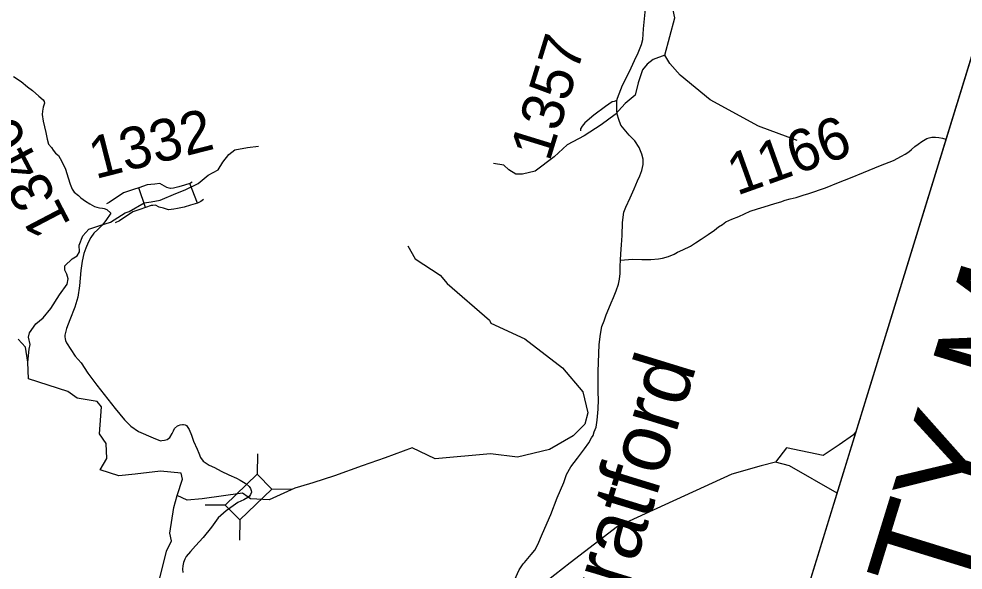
# Model space of a CAD drawing. Extents: x 1347947 to 1350662, y 1027710 to 1030532.
# Drawn here: x 1348252.2 to 1348353.5, y 1028872.1 to 1028931.2 of the extents above; entities that cross this region are included whole.
import ezdxf

# ---------------------------------------------------------------- set-up
doc = ezdxf.new("R2010")
doc.units = 0
for name, color, linetype in [('Default', 7, 'Continuous'), ('Prop Leader Line Light', 7, 'Continuous'), ('Prop WCC CELL', 7, 'Continuous')]:
    doc.layers.add(name, color=color, linetype=linetype)

msp = doc.modelspace()

# ---------------------------------------------------------------- linework, layer by layer
at = {"layer": 'Default'}
for p, q in [((1348271.33, 1028911.43), (1348270.53, 1028913.54)), ((1348265.77, 1028910.96), (1348265.04, 1028913.09)), ((1348277.79, 1028884.53), (1348277.76, 1028882.36)), ((1348281.49, 1028880.72), (1348279.31, 1028880.76)), ((1348274.36, 1028879.01), (1348272.18, 1028879.04)), ((1348275.88, 1028877.45), (1348275.84, 1028875.27))]:
    msp.add_line(p, q, dxfattribs=at)
for points in [[(1348335.7, 1028918.15), (1348331.55, 1028919.69), (1348326.36, 1028922.53), (1348323.14, 1028925.18), (1348322.03, 1028926.42), (1348321.51, 1028927.31), (1348322.57, 1028931.33), (1348321.95, 1028934.18), (1348322.52, 1028936.78), (1348322.2, 1028941.24), (1348321.28, 1028949.45), (1348318.58, 1028951.79), (1348317.29, 1028954.5)], [(1348316.36, 1028922.46), (1348316.42, 1028922.69), (1348316.97, 1028924.08), (1348317.69, 1028925.56), (1348318.26, 1028926.75), (1348318.64, 1028927.55), (1348318.98, 1028928.47), (1348319.13, 1028929.01), (1348319.2, 1028930.15), (1348319.42, 1028932.29)], [(1348321.51, 1028927.31), (1348320.24, 1028926.84), (1348319.6, 1028926.35), (1348319.09, 1028925.75), (1348318.65, 1028924.34), (1348318.3, 1028923.03), (1348317.24, 1028922.12), (1348316.18, 1028920.96), (1348314.67, 1028919.85), (1348312.83, 1028918.66), (1348311.02, 1028917.69), (1348309.63, 1028916.4), (1348307.57, 1028914.88), (1348306.22, 1028914.53), (1348305.51, 1028914.54), (1348304.76, 1028915.01), (1348304.22, 1028915.5), (1348303.1, 1028915.69)], [(1348251.59, 1028925.02), (1348252.41, 1028924.5), (1348253.09, 1028923.93), (1348253.64, 1028923.51), (1348254.31, 1028922.93), (1348254.77, 1028922.52), (1348254.89, 1028922.36), (1348254.92, 1028922.15), (1348254.77, 1028921.72), (1348254.7, 1028921.32), (1348254.69, 1028920.94), (1348254.77, 1028920.24), (1348255.06, 1028919.01), (1348255.21, 1028918.29), (1348255.37, 1028917.76), (1348255.66, 1028917.39), (1348255.86, 1028917.13), (1348256.12, 1028916.81), (1348256.42, 1028916.54), (1348256.59, 1028916.23), (1348256.75, 1028915.99), (1348257.19, 1028915.09), (1348257.48, 1028914.14), (1348257.67, 1028913.48), (1348257.9, 1028912.93), (1348258.12, 1028912.61), (1348258.56, 1028912.27), (1348258.82, 1028912.02), (1348259.34, 1028911.65), (1348259.78, 1028911.38), (1348260.3, 1028911.08), (1348260.56, 1028910.99), (1348260.84, 1028910.93), (1348261.15, 1028910.88), (1348261.33, 1028910.86), (1348261.62, 1028910.76), (1348262.05, 1028910.35)], [(1348316.36, 1028922.46), (1348316.06, 1028922.35), (1348315.86, 1028922.32), (1348315.12, 1028921.81), (1348313.89, 1028920.86), (1348312.91, 1028920.05), (1348312.61, 1028919.69), (1348312.45, 1028919.4), (1348312.43, 1028919.2)], [(1348316.74, 1028905.33), (1348316.79, 1028905.98), (1348316.85, 1028906.95), (1348316.92, 1028907.97), (1348316.96, 1028909.35), (1348317.11, 1028910.48), (1348317.3, 1028911.02), (1348317.77, 1028912.02), (1348318.19, 1028912.97), (1348318.57, 1028913.84), (1348318.81, 1028914.38), (1348319.03, 1028914.95), (1348319.19, 1028915.57), (1348319.17, 1028916.14), (1348319.04, 1028916.71), (1348318.76, 1028917.41), (1348318.28, 1028918.13), (1348317.68, 1028918.73), (1348317.12, 1028919.37), (1348316.78, 1028919.81), (1348316.56, 1028920.41), (1348316.39, 1028920.98), (1348316.35, 1028921.46), (1348316.36, 1028922.46)], [(1348316.74, 1028905.33), (1348318.01, 1028905.41), (1348319.02, 1028905.39), (1348320, 1028905.4), (1348320.83, 1028905.46), (1348321.24, 1028905.54), (1348321.89, 1028905.71), (1348322.5, 1028905.97), (1348322.85, 1028906.16), (1348323.44, 1028906.44), (1348324.25, 1028906.81), (1348324.8, 1028907.17), (1348325.41, 1028907.57), (1348326.15, 1028908.07), (1348326.82, 1028908.53), (1348327.27, 1028908.88), (1348327.7, 1028909.14), (1348328.06, 1028909.42), (1348328.7, 1028909.73), (1348329.44, 1028910.02), (1348330.65, 1028910.56), (1348331.46, 1028910.81), (1348332.17, 1028911.05), (1348332.72, 1028911.22), (1348333.29, 1028911.4), (1348333.93, 1028911.56), (1348334.41, 1028911.74), (1348334.96, 1028911.9), (1348335.58, 1028912.05), (1348336.34, 1028912.31), (1348336.94, 1028912.46), (1348338.73, 1028913.07), (1348340.12, 1028913.66), (1348341.41, 1028914.16), (1348342.82, 1028914.73), (1348344.65, 1028915.48), (1348346.02, 1028916.02), (1348346.89, 1028916.46), (1348347.28, 1028916.71), (1348347.67, 1028916.96), (1348347.98, 1028917.2), (1348348.33, 1028917.51), (1348348.68, 1028917.76), (1348349.07, 1028918.04), (1348349.42, 1028918.28), (1348349.62, 1028918.39), (1348349.88, 1028918.46), (1348350.16, 1028918.52), (1348350.53, 1028918.51), (1348350.9, 1028918.48), (1348351.29, 1028918.4), (1348351.66, 1028918.31), (1348351.69, 1028918.31)], [(1348253.12, 1028894.38), (1348253.29, 1028895.78), (1348253.39, 1028896.26), (1348253.22, 1028897.04), (1348253.32, 1028897.51), (1348253.99, 1028898.5), (1348254.8, 1028899.13), (1348255.61, 1028900.13), (1348256.52, 1028901.59), (1348257.35, 1028902.73), (1348257.45, 1028903.3), (1348257.32, 1028903.81), (1348257.1, 1028904.24), (1348257.12, 1028904.7), (1348257.9, 1028905.45), (1348258.42, 1028905.78), (1348258.67, 1028906.2), (1348258.65, 1028906.92), (1348259.05, 1028907.94), (1348259.7, 1028908.63), (1348260.86, 1028909.04), (1348262.02, 1028909.41), (1348263.58, 1028910.39), (1348264, 1028910.55), (1348265.61, 1028911.46), (1348266.36, 1028911.56), (1348267.34, 1028911.75), (1348269.02, 1028912.48), (1348270.03, 1028912.85), (1348271.41, 1028913.53), (1348272.5, 1028914.43), (1348273.58, 1028915.01), (1348274.08, 1028915.85), (1348274.71, 1028916.65), (1348275.35, 1028917.14), (1348276.7, 1028917.39), (1348277.89, 1028917.54)], [(1348270.76, 1028913.69), (1348270.58, 1028913.57), (1348270.53, 1028913.54), (1348269.96, 1028913.38), (1348269.33, 1028913.19), (1348268.77, 1028913.06), (1348268.47, 1028913.02), (1348268.44, 1028913.01), (1348268.3, 1028913.05), (1348268.06, 1028913.11), (1348267.32, 1028913.54), (1348266.77, 1028913.48), (1348266.35, 1028913.43), (1348265.93, 1028913.41), (1348265.04, 1028913.09), (1348264.46, 1028912.9), (1348263.39, 1028912.54), (1348261.86, 1028911.5), (1348261.59, 1028911.37)], [(1348272, 1028911.81), (1348271.7, 1028911.61), (1348271.33, 1028911.43), (1348270.59, 1028911.22), (1348269.9, 1028911.01), (1348269.19, 1028910.85), (1348268.81, 1028910.79), (1348268.25, 1028910.71), (1348267.7, 1028910.88), (1348267.22, 1028911), (1348266.84, 1028911.22), (1348266.54, 1028911.18), (1348266.38, 1028911.18), (1348265.77, 1028910.96), (1348265.17, 1028910.76), (1348264.4, 1028910.5), (1348262.97, 1028909.53), (1348262.52, 1028909.33)], [(1348262.05, 1028910.35), (1348261.51, 1028909.58), (1348261.1, 1028909.07), (1348260.64, 1028908.62), (1348260.23, 1028908.21), (1348259.89, 1028907.74), (1348259.6, 1028907.21), (1348259.37, 1028906.6), (1348259.16, 1028906.02), (1348258.97, 1028905.21), (1348258.82, 1028904.2), (1348258.67, 1028902.56), (1348258.51, 1028901.33), (1348258.19, 1028900.28), (1348257.65, 1028898.92), (1348257.28, 1028897.97), (1348257.12, 1028897.27), (1348257.1, 1028897.09), (1348257.13, 1028896.88), (1348257.19, 1028896.7), (1348257.3, 1028896.43), (1348258.22, 1028895.03), (1348258.86, 1028894.31), (1348259.57, 1028893.2), (1348260.53, 1028891.91), (1348262.5, 1028889.41), (1348263.5, 1028888.18), (1348264.19, 1028887.51), (1348265, 1028886.92), (1348266.58, 1028886.24), (1348267.36, 1028885.93), (1348267.53, 1028885.95), (1348267.81, 1028885.99), (1348267.95, 1028886.02), (1348268.08, 1028886.09), (1348268.22, 1028886.18), (1348268.37, 1028886.27), (1348268.62, 1028886.71), (1348268.77, 1028887.02), (1348268.89, 1028887.24), (1348269.2, 1028887.54), (1348269.29, 1028887.57), (1348269.47, 1028887.63), (1348269.73, 1028887.69), (1348269.84, 1028887.67), (1348270.01, 1028887.65), (1348270.17, 1028887.57), (1348270.45, 1028887.15), (1348270.69, 1028886.55), (1348270.93, 1028885.9), (1348271.31, 1028885.05), (1348271.5, 1028884.6), (1348271.67, 1028884.14), (1348271.94, 1028883.74), (1348272.29, 1028883.53), (1348272.6, 1028883.3), (1348273.16, 1028883.07), (1348273.9, 1028882.68), (1348274.69, 1028882.29), (1348275.52, 1028881.92), (1348275.91, 1028881.7), (1348276.47, 1028881.38), (1348276.57, 1028881.3), (1348276.88, 1028881.02), (1348277.03, 1028880.82), (1348277.11, 1028880.61), (1348277.13, 1028880.42), (1348277.05, 1028880.18), (1348276.91, 1028879.99), (1348276.78, 1028879.9)], [(1348293.93, 1028906.85), (1348294.72, 1028905.47), (1348297.4, 1028903.69), (1348298.14, 1028902.83), (1348302.68, 1028898.89), (1348302.84, 1028898.57), (1348306.47, 1028896.89), (1348310.5, 1028893.77), (1348312.71, 1028891.18), (1348313.22, 1028888.92), (1348312.91, 1028887.72), (1348311.65, 1028886.47), (1348309.11, 1028884.99), (1348305.68, 1028884.18), (1348302.79, 1028884.55), (1348296.84, 1028884), (1348294.39, 1028885.19), (1348291.5, 1028884.1), (1348289.01, 1028883.25), (1348286.06, 1028882.16), (1348283.72, 1028881.43)], [(1348305.36, 1028870.99), (1348305.86, 1028872.09), (1348306.29, 1028872.72), (1348306.43, 1028872.87), (1348307.17, 1028873.72), (1348307.53, 1028874.2), (1348307.88, 1028874.82), (1348308.38, 1028875.97), (1348309.27, 1028878.04), (1348309.95, 1028879.8), (1348310.65, 1028881.47), (1348310.96, 1028882.32), (1348311.41, 1028883.15), (1348312.13, 1028884.07), (1348312.89, 1028885.08), (1348313.33, 1028885.71), (1348313.64, 1028886.25), (1348313.8, 1028886.49), (1348313.93, 1028886.89), (1348314.13, 1028887.38), (1348314.23, 1028888.14), (1348314.34, 1028889.33), (1348314.37, 1028890.36), (1348314.34, 1028891.12), (1348314.35, 1028893.38), (1348314.45, 1028896.28), (1348314.58, 1028897.39), (1348314.75, 1028898.19), (1348315, 1028898.81), (1348315.2, 1028899.44), (1348315.47, 1028900.12), (1348315.75, 1028900.75), (1348316, 1028901.31), (1348316.27, 1028902.01), (1348316.51, 1028902.74), (1348316.65, 1028903.29), (1348316.7, 1028903.88), (1348316.72, 1028904.2), (1348316.72, 1028904.68), (1348316.74, 1028905.33)], [(1348269.15, 1028880.07), (1348269.72, 1028881.83), (1348269.59, 1028882.45), (1348267.39, 1028882.68), (1348264.66, 1028882.34), (1348262.9, 1028882.18), (1348260.91, 1028882.83), (1348261.61, 1028884.04), (1348261.56, 1028885.64), (1348260.82, 1028886.67), (1348261.04, 1028889.57), (1348260.57, 1028890.15), (1348258.44, 1028890.5), (1348257.44, 1028891.24), (1348253.2, 1028892.6), (1348253.12, 1028894.38), (1348252.9, 1028895.98), (1348252.1, 1028896.85)], [(1348342.48, 1028888.41), (1348342.46, 1028888.39), (1348342.45, 1028888.3)], [(1348342.04, 1028886.98), (1348341.75, 1028886.58), (1348340.21, 1028885.5), (1348338.48, 1028884.36), (1348334.56, 1028885.18), (1348333.37, 1028883.64)], [(1348333.37, 1028883.64), (1348331.83, 1028883.24), (1348328.68, 1028882.36), (1348316.42, 1028876.72), (1348311.33, 1028872.83), (1348308.86, 1028870.92), (1348308.06, 1028870.18), (1348306.64, 1028868.69), (1348305.18, 1028867.21), (1348304.9, 1028866.11), (1348305.29, 1028864.31)], [(1348339.99, 1028880.33), (1348334.86, 1028883.24), (1348333.37, 1028883.64)], [(1348283.72, 1028881.43), (1348283.37, 1028881.32), (1348281.78, 1028880.86), (1348279.02, 1028879.61), (1348277.03, 1028879.69), (1348276.78, 1028879.9)], [(1348271.18, 1028865.33), (1348270.97, 1028865.29), (1348270.31, 1028865.1), (1348269.9, 1028864.8), (1348269.38, 1028864.48), (1348269.13, 1028864.38), (1348268.93, 1028864.32), (1348268.37, 1028864.48), (1348267.5, 1028864.83), (1348266.57, 1028865.4), (1348264.87, 1028866.34), (1348263.98, 1028866.86), (1348264.61, 1028868.51), (1348264.61, 1028869.45), (1348267.27, 1028871.06), (1348268.01, 1028874.08), (1348268.57, 1028875.2), (1348268.36, 1028876.03), (1348268.81, 1028878.77), (1348269.15, 1028880.07)], [(1348276.78, 1028879.9), (1348276.19, 1028880.31), (1348271.85, 1028879.71), (1348270.23, 1028879.57), (1348269.15, 1028880.07)], [(1348276.78, 1028879.9), (1348276.73, 1028879.84), (1348276.33, 1028879.61), (1348275.69, 1028879.3), (1348275.17, 1028878.97), (1348274.42, 1028878.41), (1348273.56, 1028877.67), (1348272.84, 1028876.67), (1348271.97, 1028875.57), (1348271.12, 1028874.66), (1348270.6, 1028874.06), (1348270.13, 1028873.5), (1348270, 1028873.24), (1348269.83, 1028872.88), (1348269.76, 1028872.52), (1348269.75, 1028872.17), (1348269.78, 1028871.81)]]:
    msp.add_lwpolyline(points, dxfattribs=at)
msp.add_lwpolyline([(1348279.31, 1028880.76), (1348275.88, 1028877.44), (1348274.33, 1028879.04), (1348277.76, 1028882.36)], close=True, dxfattribs=at)
at = {"layer": 'Prop WCC CELL'}
msp.add_line((1348285.23, 1028702.5), (1348393.41, 1029053.78), dxfattribs=at)
msp.add_lwpolyline([(1348285.23, 1028702.5), (1348393.41, 1029053.78), (1348428.36, 1029043.07), (1348320.15, 1028691.84)], close=True, dxfattribs=at)

# ---------------------------------------------------------------- texts
at = {"layer": 'Prop Leader Line Light'}
for s, height, rotation, p in [('1357', 4.5, 72.8834, (1348309.12, 1028915.79)), ('VICINITY MAP', 11.25, 72.8834, (1348340.8, 1028825.9)), ('1332', 4.5, 14.3091, (1348260.37, 1028914)), ('1346', 4.5, 117.6348, (1348257.83, 1028909.18)), ('1166', 4.5, 19.7092, (1348329.23, 1028912.22)), ('Stratford', 6.5, 72.8834, (1348315.12, 1028862.11))]:
    msp.add_text(s, height=height, rotation=rotation, dxfattribs=at).set_placement(p)

doc.saveas('drawing.dxf')
